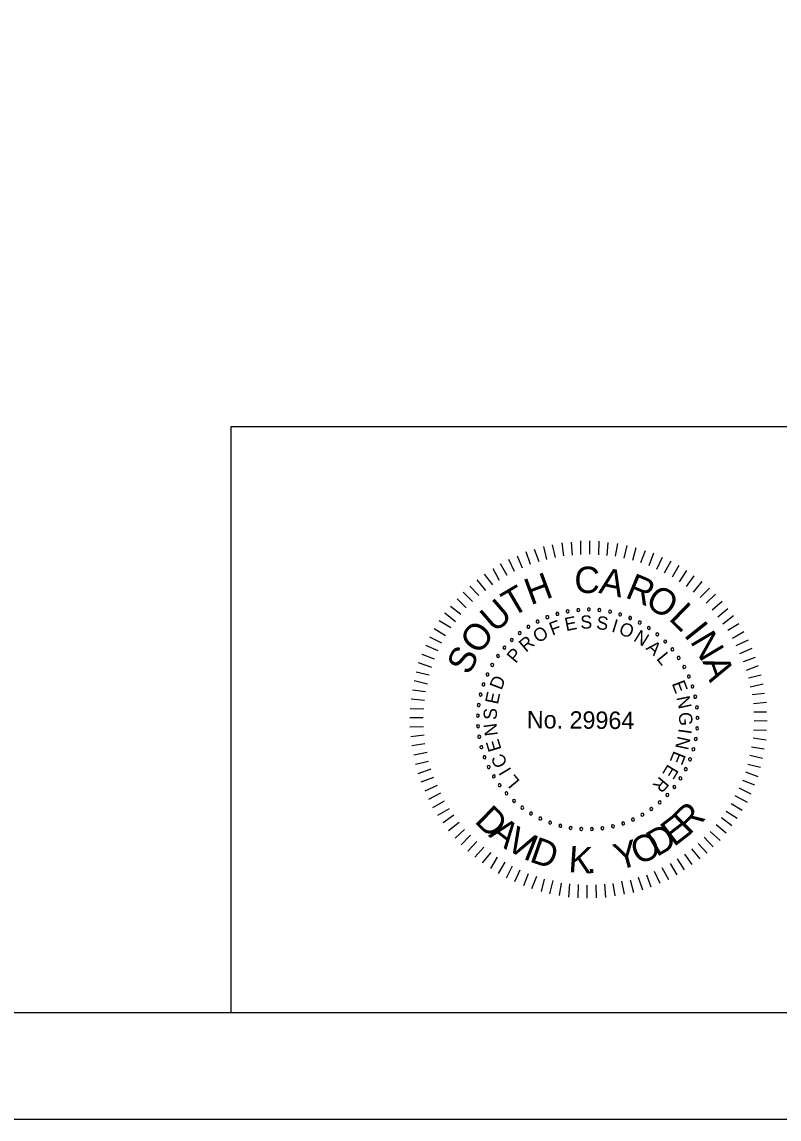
# Model space of a CAD drawing. Extents: x -125.5 to -89.4, y -5.1 to 16.9.
# Drawn here: x -103.88 to -100.33, y -5.07 to 0.08 of the extents above; entities that cross this region are included whole.
import ezdxf

# ---------------------------------------------------------------- set-up
doc = ezdxf.new("R2010")
doc.units = 0
for name, color, linetype in [('BR_BORDER LINES', 7, 'Continuous'), ('BR_TEXT', 7, 'Continuous'), ('Level 31', 7, 'Continuous')]:
    doc.layers.add(name, color=color, linetype=linetype)

msp = doc.modelspace()

# ---------------------------------------------------------------- linework, layer by layer
at = {"layer": 'BR_BORDER LINES'}
for p, q in [((-102.8989, -1.8161), (-97.5337, -1.8161)), ((-102.8989, -4.5661), (-102.8989, -1.8161)), ((-123.6994, -4.5662), (-90.0334, -4.5662))]:
    msp.add_line(p, q, dxfattribs=at)
at = {"layer": 'BR_TEXT'}
for p, q in [((-101.3372, -2.423), (-101.3461, -2.362)), ((-101.2977, -2.419), (-101.3015, -2.3581)), ((-101.2582, -2.4168), (-101.2576, -2.3524)), ((-101.2161, -2.4146), (-101.2156, -2.3528)), ((-101.1741, -2.4175), (-101.1718, -2.3531)), ((-101.1338, -2.4204), (-101.129, -2.3595)), ((-101.0952, -2.425), (-101.0844, -2.3642)), ((-101.4937, -2.4629), (-101.5147, -2.4044)), ((-101.4541, -2.4504), (-101.476, -2.3927)), ((-101.418, -2.4404), (-101.4312, -2.3793)), ((-101.3767, -2.4304), (-101.3908, -2.3711)), ((-101.0549, -2.4331), (-101.0407, -2.374)), ((-101.0138, -2.4437), (-100.9979, -2.3829)), ((-100.977, -2.4543), (-100.9551, -2.397)), ((-100.9376, -2.4675), (-100.9157, -2.4093)), ((-101.604, -2.5144), (-101.6344, -2.46)), ((-101.5695, -2.4966), (-101.5957, -2.4406)), ((-101.5325, -2.4798), (-101.556, -2.4238)), ((-100.9017, -2.485), (-100.8738, -2.4294)), ((-100.8658, -2.5024), (-100.8345, -2.4469)), ((-100.8282, -2.5208), (-100.796, -2.467)), ((-101.6704, -2.5593), (-101.7095, -2.5083)), ((-101.6394, -2.5381), (-101.6698, -2.4838)), ((-100.795, -2.5451), (-100.761, -2.4913)), ((-100.7617, -2.5668), (-100.7252, -2.5165)), ((-101.7369, -2.6094), (-101.7786, -2.5644)), ((-101.7041, -2.5847), (-101.744, -2.5346)), ((-100.7293, -2.5928), (-100.6886, -2.5434)), ((-100.6977, -2.618), (-100.6545, -2.5737)), ((-101.7958, -2.6673), (-101.8392, -2.6248)), ((-101.7663, -2.6366), (-101.8106, -2.5925)), ((-100.6697, -2.6456), (-100.6264, -2.6022)), ((-101.8209, -2.6988), (-101.8704, -2.6598)), ((-100.6416, -2.6768), (-100.594, -2.6351)), ((-100.6144, -2.7088), (-100.5677, -2.6705)), ((-101.8686, -2.761), (-101.9224, -2.728)), ((-101.8469, -2.732), (-101.8964, -2.6922)), ((-100.5906, -2.7424), (-100.5414, -2.7033)), ((-101.893, -2.7977), (-101.9467, -2.7656)), ((-100.5686, -2.7718), (-100.516, -2.7396)), ((-100.5466, -2.8089), (-100.4931, -2.7776)), ((-101.9104, -2.8319), (-101.9668, -2.804)), ((-100.5288, -2.8433), (-100.4711, -2.8164)), ((-101.9279, -2.8687), (-101.9851, -2.8433)), ((-100.5111, -2.8804), (-100.4542, -2.856)), ((-101.9577, -2.9474), (-102.0193, -2.9246)), ((-101.9454, -2.9072), (-102.0035, -2.8852)), ((-100.4943, -2.9192), (-100.4374, -2.8982)), ((-101.97, -2.9833), (-102.0308, -2.9682)), ((-100.4809, -2.9596), (-100.4232, -2.9378)), ((-100.4708, -2.9957), (-100.4107, -2.9816)), ((-101.9772, -3.0253), (-102.0397, -3.0094)), ((-100.4626, -3.0378), (-100.4024, -3.0229)), ((-101.9878, -3.0613), (-102.0487, -3.0531)), ((-100.4543, -3.074), (-100.3951, -3.0667)), ((-101.9925, -3.1024), (-102.0542, -3.0951)), ((-100.4478, -3.1152), (-100.3868, -3.1088)), ((-101.9974, -3.183), (-102.06, -3.1825)), ((-101.9954, -3.1419), (-102.0597, -3.1414)), ((-100.4464, -3.1547), (-100.3863, -3.1552)), ((-101.9961, -3.226), (-102.0604, -3.2272)), ((-100.4471, -3.2388), (-100.3871, -3.241)), ((-100.4442, -3.1959), (-100.3833, -3.1964)), ((-101.9938, -3.2646), (-102.0556, -3.2718)), ((-100.4492, -3.2774), (-100.3883, -3.2856)), ((-101.9898, -3.3058), (-102.0509, -3.3148)), ((-101.9799, -3.3454), (-102.0426, -3.3586)), ((-100.4563, -3.3185), (-100.3972, -3.3284)), ((-101.9733, -3.3875), (-102.0344, -3.4016)), ((-100.4653, -3.3579), (-100.4053, -3.3721)), ((-101.9616, -3.4245), (-102.0236, -3.4454)), ((-100.4848, -3.4367), (-100.4275, -3.4586)), ((-100.4742, -3.3999), (-100.4143, -3.415)), ((-101.95, -3.4632), (-102.0085, -3.4842)), ((-101.9331, -3.5003), (-101.9908, -3.5272)), ((-100.4989, -3.4752), (-100.4424, -3.4971)), ((-101.9162, -3.5364), (-101.9731, -3.566)), ((-100.5346, -3.5479), (-100.4774, -3.5784)), ((-100.5163, -3.512), (-100.4599, -3.5399)), ((-101.8994, -3.5735), (-101.9537, -3.6048)), ((-100.553, -3.5846), (-100.5, -3.6168)), ((-101.8756, -3.6106), (-101.93, -3.6419)), ((-101.8544, -3.6399), (-101.9045, -3.6764)), ((-100.5981, -3.6503), (-100.5495, -3.6876)), ((-100.5756, -3.6213), (-100.5235, -3.6535)), ((-101.829, -3.6736), (-101.8791, -3.7127)), ((-101.8043, -3.7073), (-101.8485, -3.7481)), ((-100.6224, -3.6836), (-100.5764, -3.7234)), ((-101.7754, -3.7333), (-101.8204, -3.7784)), ((-100.6787, -3.7424), (-100.6362, -3.7882)), ((-100.6502, -3.7168), (-100.6033, -3.7584)), ((-101.7465, -3.7636), (-101.7889, -3.8095)), ((-101.714, -3.7895), (-101.7548, -3.8364)), ((-100.7392, -3.7976), (-100.6993, -3.8452)), ((-100.7073, -3.7721), (-100.6648, -3.8188)), ((-101.6808, -3.8156), (-101.7207, -3.8633)), ((-101.6501, -3.8373), (-101.6814, -3.8894)), ((-101.6151, -3.8599), (-101.6464, -3.9137)), ((-100.8057, -3.8443), (-100.7727, -3.8969)), ((-100.772, -3.8231), (-100.7364, -3.8714)), ((-101.5809, -3.8799), (-101.608, -3.9355)), ((-101.5442, -3.8974), (-101.5687, -3.953)), ((-100.9134, -3.9026), (-100.8865, -3.9586)), ((-100.8773, -3.8857), (-100.8468, -3.9418)), ((-100.8393, -3.8663), (-100.808, -3.9206)), ((-101.5057, -3.9149), (-101.5276, -3.9713)), ((-101.4663, -3.9272), (-101.4891, -3.9854)), ((-101.4304, -3.9395), (-101.4446, -3.9986)), ((-101.3892, -3.9467), (-101.4044, -4.0084)), ((-101.3499, -3.9582), (-101.3598, -4.0165)), ((-101.3104, -3.9628), (-101.3152, -4.0246)), ((-101.1465, -3.9642), (-101.1428, -4.026)), ((-101.1079, -3.9602), (-101.098, -4.0186)), ((-101.0674, -3.9494), (-101.0542, -4.0113)), ((-101.0262, -3.9429), (-101.0112, -4.0022)), ((-100.9892, -3.9311), (-100.9682, -3.9897)), ((-100.9496, -3.9194), (-100.9286, -3.9763)), ((-101.271, -3.9657), (-101.2715, -4.0275)), ((-101.229, -3.9686), (-101.2295, -4.0296)), ((-101.1869, -3.9664), (-101.1857, -4.0282))]:
    msp.add_line(p, q, dxfattribs=at)
for centre, start, end in [((-101.3196, -2.6831), 10.6038, 190.6038), ((-101.2702, -2.6764), 5.0653, 185.0653), ((-101.2702, -2.6764), 185.0653, 5.0653), ((-101.2204, -2.6745), 359.5268, 179.5268), ((-101.2204, -2.6745), 179.5268, 359.5268), ((-101.1707, -2.6774), 173.9884, 353.9884), ((-101.1707, -2.6774), 353.9884, 173.9884), ((-101.4607, -2.7311), 27.2191, 207.2191), ((-101.4607, -2.7311), 207.2191, 27.2191), ((-101.4153, -2.7106), 21.6807, 201.6807), ((-101.4153, -2.7106), 201.6807, 21.6807), ((-101.3681, -2.6945), 16.1422, 196.1422), ((-101.3681, -2.6945), 196.1422, 16.1422), ((-101.3196, -2.6831), 190.6038, 10.6038), ((-101.1214, -2.6851), 168.4499, 348.4499), ((-101.1214, -2.6851), 348.4499, 168.4499), ((-101.0732, -2.6976), 162.9114, 342.9114), ((-101.0732, -2.6976), 342.9114, 162.9114), ((-101.0263, -2.7146), 157.373, 337.373), ((-101.0263, -2.7146), 337.373, 157.373), ((-100.9814, -2.736), 331.8345, 151.8345), ((-101.5445, -2.7848), 38.2961, 218.2961), ((-101.5445, -2.7848), 218.2961, 38.2961), ((-101.5039, -2.7559), 32.7576, 212.7576), ((-101.5039, -2.7559), 212.7576, 32.7576), ((-100.9814, -2.736), 151.8345, 331.8345), ((-100.9387, -2.7617), 146.2961, 326.2961), ((-100.9387, -2.7617), 326.2961, 146.2961), ((-101.5821, -2.8175), 43.8345, 223.8345), ((-101.5821, -2.8175), 223.8345, 43.8345), ((-100.8987, -2.7914), 140.7576, 320.7576), ((-100.8987, -2.7914), 320.7576, 140.7576), ((-100.8617, -2.8249), 135.2191, 315.2191), ((-100.8617, -2.8249), 315.2191, 135.2191), ((-101.6164, -2.8536), 49.373, 229.373), ((-101.6164, -2.8536), 229.373, 49.373), ((-100.8281, -2.8617), 129.6807, 309.6807), ((-100.8281, -2.8617), 309.6807, 129.6807), ((-101.6738, -2.935), 60.4499, 240.4499), ((-101.6738, -2.935), 240.4499, 60.4499), ((-101.6471, -2.8929), 54.9114, 234.9114), ((-101.6471, -2.8929), 234.9114, 54.9114), ((-100.7983, -2.9016), 124.1422, 304.1422), ((-100.7983, -2.9016), 304.1422, 124.1422), ((-101.6964, -2.9794), 65.9884, 245.9884), ((-101.6964, -2.9794), 245.9884, 65.9884), ((-100.7724, -2.9442), 118.6038, 298.6038), ((-100.7724, -2.9442), 298.6038, 118.6038), ((-100.7508, -2.9891), 113.0653, 293.0653), ((-100.7508, -2.9891), 293.0653, 113.0653), ((-101.7145, -3.0258), 71.5268, 251.5268), ((-101.7145, -3.0258), 251.5268, 71.5268), ((-100.7336, -3.0359), 107.5268, 287.5268), ((-100.7336, -3.0359), 287.5268, 107.5268), ((-101.7281, -3.0738), 77.0653, 257.0653), ((-101.7281, -3.0738), 257.0653, 77.0653), ((-100.721, -3.0841), 101.9884, 281.9884), ((-100.721, -3.0841), 281.9884, 101.9884), ((-101.737, -3.1228), 82.6038, 262.6038), ((-101.737, -3.1228), 262.6038, 82.6038), ((-100.7131, -3.1333), 96.4499, 276.4499), ((-100.7131, -3.1333), 276.4499, 96.4499), ((-101.7411, -3.1724), 88.1422, 268.1422), ((-101.7411, -3.1724), 268.1422, 88.1422), ((-100.71, -3.183), 90.9114, 270.9114), ((-100.71, -3.183), 270.9114, 90.9114), ((-101.7404, -3.2223), 93.6807, 273.6807), ((-101.7404, -3.2223), 273.6807, 93.6807), ((-100.7118, -3.2328), 85.373, 265.373), ((-100.7118, -3.2328), 265.373, 85.373), ((-101.7349, -3.2718), 99.2191, 279.2191), ((-101.7349, -3.2718), 279.2191, 99.2191), ((-100.7183, -3.2822), 79.8345, 259.8345), ((-100.7183, -3.2822), 259.8345, 79.8345), ((-101.7246, -3.3206), 104.7576, 284.7576), ((-101.7246, -3.3206), 284.7576, 104.7576), ((-100.7295, -3.3308), 74.2961, 254.2961), ((-100.7295, -3.3308), 254.2961, 74.2961), ((-101.7097, -3.3681), 110.2961, 290.2961), ((-101.7097, -3.3681), 290.2961, 110.2961), ((-100.7454, -3.378), 68.7576, 248.7576), ((-100.7454, -3.378), 248.7576, 68.7576), ((-101.6903, -3.414), 115.8345, 295.8345), ((-101.6903, -3.414), 295.8345, 115.8345), ((-100.7658, -3.4235), 63.2191, 243.2191), ((-100.7658, -3.4235), 243.2191, 63.2191), ((-101.6665, -3.4578), 121.373, 301.373), ((-101.6665, -3.4578), 301.373, 121.373), ((-101.6386, -3.4991), 126.9114, 306.9114), ((-101.6386, -3.4991), 306.9114, 126.9114), ((-100.8192, -3.5075), 52.1422, 232.1422), ((-100.7904, -3.4668), 57.6807, 237.6807), ((-100.7904, -3.4668), 237.6807, 57.6807), ((-101.6069, -3.5375), 132.4499, 312.4499), ((-101.6069, -3.5375), 312.4499, 132.4499), ((-100.8517, -3.5452), 46.6038, 226.6038), ((-100.8517, -3.5452), 226.6038, 46.6038), ((-100.8192, -3.5075), 232.1422, 52.1422), ((-101.5716, -3.5727), 137.9884, 317.9884), ((-101.5716, -3.5727), 317.9884, 137.9884), ((-101.5331, -3.6043), 143.5268, 323.5268), ((-101.5331, -3.6043), 323.5268, 143.5268), ((-100.9269, -3.6105), 35.5268, 215.5268), ((-100.8877, -3.5797), 41.0653, 221.0653), ((-100.8877, -3.5797), 221.0653, 41.0653), ((-101.4917, -3.632), 149.0653, 329.0653), ((-101.4917, -3.632), 329.0653, 149.0653), ((-101.4478, -3.6556), 154.6038, 334.6038), ((-101.4478, -3.6556), 334.6038, 154.6038), ((-101.0132, -3.6601), 24.4499, 204.4499), ((-100.9688, -3.6374), 29.9884, 209.9884), ((-100.9688, -3.6374), 209.9884, 29.9884), ((-100.9269, -3.6105), 215.5268, 35.5268), ((-101.4018, -3.6749), 160.1422, 340.1422), ((-101.4018, -3.6749), 340.1422, 160.1422), ((-101.3542, -3.6896), 165.6807, 345.6807), ((-101.3542, -3.6896), 345.6807, 165.6807), ((-101.3054, -3.6997), 351.2191, 171.2191), ((-101.3054, -3.6997), 171.2191, 351.2191), ((-101.2559, -3.705), 356.7576, 176.7576), ((-101.2559, -3.705), 176.7576, 356.7576), ((-101.2061, -3.7055), 2.2961, 182.2961), ((-101.2061, -3.7055), 182.2961, 2.2961), ((-101.1564, -3.7012), 7.8345, 187.8345), ((-101.1564, -3.7012), 187.8345, 7.8345), ((-101.1074, -3.6921), 13.373, 193.373), ((-101.1074, -3.6921), 193.373, 13.373), ((-101.0595, -3.6784), 18.9114, 198.9114), ((-101.0595, -3.6784), 198.9114, 18.9114), ((-101.0132, -3.6601), 204.4499, 24.4499)]:
    msp.add_arc(centre, 0.00701, start, end, dxfattribs=at)
at = {"layer": 'Level 31'}
msp.add_lwpolyline([(-125.5328, -5.0661), (-89.5328, -5.0661), (-89.5328, 16.9339), (-125.5328, 16.9339)], close=True, dxfattribs=at)

# ---------------------------------------------------------------- texts
at = {"layer": 'BR_TEXT'}
for s, height, rotation, p in [('C', 0.1241, 359.5482, (-101.2889, -2.5969)), ('H', 0.1241, 20.3637, (-101.4933, -2.6552)), ('A', 0.1241, 348.1981, (-101.1775, -2.5961)), ('R', 0.1241, 337.4344, (-101.0542, -2.616)), ('T', 0.1241, 30.4992, (-101.5812, -2.7128)), ('O', 0.1239, 326.5869, (-100.962, -2.6528)), ('U', 0.1241, 40.8022, (-101.6624, -2.7875)), ('L', 0.1241, 315.9488, (-100.8494, -2.7205)), ('F', 0.0622, 20.6127, (-101.392, -2.7981)), ('E', 0.0622, 11.4103, (-101.3269, -2.7764)), ('S', 0.0622, 2.208, (-101.2591, -2.7654)), ('S', 0.0622, 352.6608, (-101.1878, -2.7657)), ('I', 0.0622, 343.1136, (-101.1175, -2.7777)), ('O', 0.1241, 52.0267, (-101.7369, -2.8914)), ('O', 0.0622, 30.8477, (-101.4594, -2.8341)), ('O', 0.0622, 338.4392, (-101.0841, -2.7878)), ('N', 0.0622, 328.2042, (-101.0145, -2.8192)), ('I', 0.1241, 308.6613, (-100.778, -2.7948)), ('N', 0.1241, 300.7037, (-100.7474, -2.8242)), ('R', 0.0622, 40.3949, (-101.5156, -2.878)), ('A', 0.0622, 318.657, (-100.9555, -2.8592)), ('S', 0.1239, 63.2511, (-101.7823, -2.9871)), ('P', 0.0622, 49.9421, (-101.5636, -2.9306)), ('L', 0.0622, 309.4546, (-100.9057, -2.9066)), ('A', 0.1241, 289.4792, (-100.6882, -2.9172)), ('D', 0.0622, 69.0364, (-101.6306, -3.0559)), ('E', 0.0622, 291.049, (-100.8319, -3.0219)), ('E', 0.0622, 78.2388, (-101.6472, -3.1226)), ('N', 0.0622, 281.8466, (-100.8097, -3.0869)), ('S', 0.0622, 87.786, (-101.6529, -3.1936)), ('No. 29964', 0.08175, 359.5268, (-101.5117, -3.232)), ('G', 0.0622, 272.2995, (-100.7979, -3.1572)), ('N', 0.0622, 97.3332, (-101.6467, -3.2646)), ('I', 0.0622, 262.4084, (-100.7983, -3.231)), ('E', 0.0622, 106.5355, (-101.6297, -3.3312)), ('N', 0.0622, 257.7339, (-100.8028, -3.2656)), ('E', 0.0622, 248.1867, (-100.8209, -3.3346)), ('C', 0.0622, 116.4266, (-101.5998, -3.3987)), ('I', 0.0622, 121.1011, (-101.5818, -3.4285)), ('L', 0.0622, 129.9595, (-101.5411, -3.4807)), ('E', 0.0622, 238.9844, (-100.8488, -3.3973)), ('R', 0.0622, 229.782, (-100.8865, -3.4548)), ('D', 0.1236, 315.4053, (-101.7616, -3.6713)), ('R', 0.1236, 44.5947, (-100.7507, -3.7369)), ('E', 0.1236, 37.5339, (-100.8213, -3.7908)), ('A', 0.1236, 322.8377, (-101.695, -3.737)), ('V', 0.1236, 330.5179, (-101.6178, -3.7952)), ('D', 0.1236, 30.1015, (-100.9022, -3.8377)), ('I', 0.1236, 338.1981, (-101.5336, -3.8425)), ('D', 0.1236, 340.7995, (-101.5037, -3.856)), ('Y', 0.1236, 14.8649, (-101.0833, -3.8993)), ('O', 0.1236, 22.4212, (-100.9915, -3.8748)), ('K', 0.1236, 356.098, (-101.3185, -3.9065)), ('.', 0.1236, 3.1588, (-101.2299, -3.9128))]:
    msp.add_text(s, height=height, rotation=rotation, dxfattribs=at).set_placement(p)

doc.saveas('drawing.dxf')
